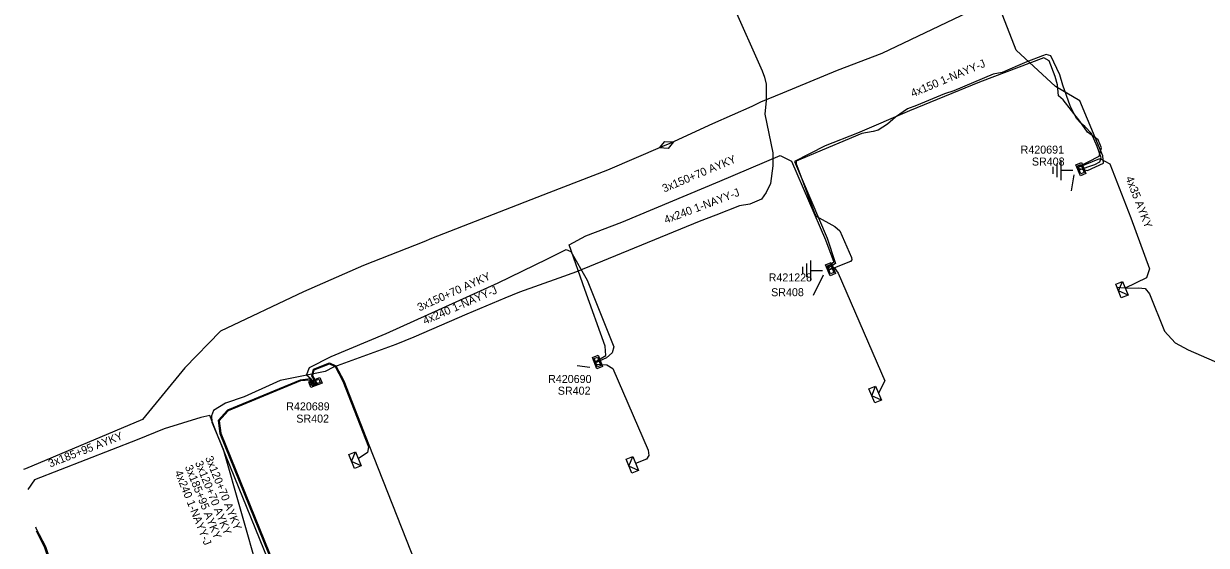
# Model space of a CAD drawing. Extents: x -540028 to -538776, y -1157064 to -1155670.
# Drawn here: x -539966.3 to -539818.5, y -1156244.1 to -1156179 of the extents above; entities that cross this region are included whole.
import ezdxf

# ---------------------------------------------------------------- set-up
doc = ezdxf.new("R2010")
doc.units = 0
for name, color, linetype in [('Vrstva 15', 7, 'Continuous'), ('Vrstva 19', 7, 'Continuous'), ('Vrstva 2', 7, 'Continuous'), ('Vrstva 28', 7, 'Continuous'), ('Vrstva 29', 7, 'Continuous'), ('Vrstva 30', 7, 'Continuous'), ('Vrstva 31', 7, 'Continuous'), ('Vrstva 5', 7, 'Continuous'), ('Vrstva 52', 7, 'Continuous'), ('Vrstva 59', 7, 'Continuous'), ('Vrstva 6', 7, 'Continuous'), ('Vrstva 9', 7, 'Continuous')]:
    doc.layers.add(name, color=color, linetype=linetype)

# ---------------------------------------------------------------- blocks, each defined once
blk = doc.blocks.new('17')
at = {"layer": 'Vrstva 2'}
blk.add_lwpolyline([(-1.875, 0), (0, 0.9375), (1.875, 0), (0, -0.9375)], close=True, dxfattribs=at)
blk = doc.blocks.new('132')
at = {"layer": 'Vrstva 2'}
for points in [[(-1.5, 1.5), (1.5, 1.5), (1.5, 0), (-1.5, 0)], [(-1.1, 1.2), (1.1, 1.2), (1.1, 0.3), (-1.1, 0.3)]]:
    blk.add_lwpolyline(points, close=True, dxfattribs=at)
blk = doc.blocks.new('23')
at = {"layer": 'Vrstva 2'}
blk.add_lwpolyline([(1.875, -1.8), (-1.875, -1.8), (-1.875, 0), (1.875, 0)], close=True, dxfattribs=at)
blk.add_lwpolyline([(1.875, 0), (0, -1.8), (-1.875, 0)], dxfattribs=at)
blk = doc.blocks.new('11')
at = {"layer": 'Vrstva 2'}
for p, q in [((0, -4.3), (0, -1.3)), ((-2.5, -4.3), (2.5, -4.3)), ((-1.7, -5.3), (1.7, -5.3)), ((-0.9, -6.3), (0.9, -6.3))]:
    blk.add_line(p, q, dxfattribs=at)

msp = doc.modelspace()

# ---------------------------------------------------------------- linework, layer by layer
at = {"layer": 'Vrstva 5'}
for points in [[(-539834.5, -1156197.03), (-539833.31, -1156197.31), (-539831.32, -1156196.41), (-539831.41, -1156195.48), (-539834.3, -1156188.62), (-539837.34, -1156186.81), (-539842.25, -1156182.27), (-539845.64, -1156173.48), (-539848.98, -1156165.28), (-539851.72, -1156160.92)], [(-539877.72, -1156176.54), (-539873.98, -1156184.89), (-539873.7, -1156185.67), (-539873.48, -1156186.52), (-539873.48, -1156187.09), (-539873.5, -1156188.58), (-539873.64, -1156190.3), (-539872.66, -1156195.09), (-539872.65, -1156196.75), (-539872.93, -1156198.93), (-539873.5, -1156200.06), (-539874.08, -1156200.88), (-539875.55, -1156201.51), (-539876.81, -1156201.72), (-539879.78, -1156202.89), (-539881.88, -1156203.69), (-539897.18, -1156209.96), (-539899.42, -1156210.75), (-539904.32, -1156212.53), (-539905.25, -1156212.89), (-539906.15, -1156213.25), (-539910.9, -1156215.24), (-539917.52, -1156218.12), (-539919.76, -1156219.06), (-539927.59, -1156221.86), (-539928.62, -1156222.41), (-539934.23, -1156223.55), (-539935.17, -1156223.94), (-539938.74, -1156225.58), (-539941.06, -1156226.39), (-539942.55, -1156227.29), (-539942.82, -1156227.94), (-539942.76, -1156228.74), (-539941.38, -1156232.1), (-539936.93, -1156247.59)], [(-539848.27, -1156177.59), (-539859.05, -1156182.72), (-539864.62, -1156184.81), (-539871.44, -1156187.67), (-539874.19, -1156188.77), (-539874.37, -1156188.87), (-539875.3, -1156189.31), (-539880.22, -1156191.49), (-539885.53, -1156193.93), (-539886.44, -1156194.34), (-539893.34, -1156197.26), (-539900.64, -1156200.09), (-539915.32, -1156205.82), (-539916.28, -1156206.22), (-539923.81, -1156209.19), (-539931.32, -1156212.47), (-539941.68, -1156217.37), (-539946.15, -1156221.96), (-539951.45, -1156228.42), (-539966.08, -1156234.56), (-539966.3, -1156234.65)], [(-539834.5, -1156197.29), (-539832.42, -1156196.58), (-539831.8, -1156196.23), (-539831.63, -1156195.74), (-539832.12, -1156194.3), (-539832.81, -1156192.68), (-539833.67, -1156191.83), (-539834.12, -1156191.45), (-539834.69, -1156190.83), (-539835.5, -1156189.25), (-539836.4, -1156186.67), (-539836.8, -1156185.39), (-539837.92, -1156182.99), (-539838.51, -1156182.83), (-539838.95, -1156182.98), (-539840.92, -1156183.74), (-539842.09, -1156184.24), (-539844, -1156185.06), (-539845.12, -1156185.3), (-539850.04, -1156187.37), (-539851.2, -1156187.74), (-539854.7, -1156189.2), (-539855.83, -1156189.6), (-539857.32, -1156190.65), (-539858.34, -1156191.52), (-539859.48, -1156192.27), (-539860.11, -1156192.45), (-539861.55, -1156192.68), (-539868.08, -1156195.44), (-539869.76, -1156196.16), (-539869.73, -1156196.5), (-539869.14, -1156198.02), (-539868.69, -1156199.27), (-539867.46, -1156202.64), (-539867.23, -1156203), (-539864.93, -1156204.3), (-539864.3, -1156204.86), (-539862.83, -1156208.17), (-539862.79, -1156208.46), (-539862.97, -1156208.7), (-539865.79, -1156209.79)], [(-539894.95, -1156221.24), (-539893.55, -1156220.43), (-539893.6, -1156219.25), (-539896.15, -1156212.19), (-539898.12, -1156206.58), (-539896.04, -1156205.47), (-539891.52, -1156203.78), (-539879.3, -1156198.64), (-539871.73, -1156195.45), (-539870.34, -1156196.15), (-539866.07, -1156205.96), (-539865.05, -1156208.78), (-539865.88, -1156209.4)], [(-539834.53, -1156196.96), (-539831.77, -1156195.81), (-539830.55, -1156196.49), (-539827.93, -1156203.22), (-539825.58, -1156209.6), (-539825.94, -1156210.72), (-539828.61, -1156212.03)], [(-539929.75, -1156224.13), (-539930.35, -1156223.39), (-539930.96, -1156222.89), (-539930.58, -1156221.91), (-539927.85, -1156220.55), (-539921, -1156217.68), (-539907.01, -1156211.35), (-539900.91, -1156208.39), (-539898.49, -1156207.2), (-539897.9, -1156207.44), (-539895.86, -1156211.03), (-539892.52, -1156219.35), (-539892.74, -1156220.09), (-539893.43, -1156220.72), (-539894.9, -1156221.36)], [(-539929.85, -1156224.17), (-539930.45, -1156223.35), (-539931.74, -1156223.48), (-539940.8, -1156227.24), (-539942, -1156228.53), (-539941.76, -1156230.14), (-539929.6, -1156260.15), (-539927.94, -1156263.7), (-539922.13, -1156271.08), (-539920.05, -1156273.79), (-539918.56, -1156277.25), (-539918.64, -1156280.6), (-539919.35, -1156284.8), (-539918.71, -1156288.03), (-539918.53, -1156290.1), (-539919.21, -1156291.58), (-539920.51, -1156292.49), (-539932.04, -1156296.91), (-539942.01, -1156300.99)], [(-539929.97, -1156224.22), (-539930.51, -1156223.48), (-539931.71, -1156223.6), (-539940.73, -1156227.34), (-539941.88, -1156228.57), (-539941.64, -1156230.11), (-539929.49, -1156260.1), (-539927.84, -1156263.64), (-539922.03, -1156271.01), (-539919.95, -1156273.72), (-539918.44, -1156277.16), (-539918.51, -1156280.66), (-539919.17, -1156284.83), (-539918.59, -1156287.98), (-539918.37, -1156290.17), (-539919.25, -1156291.69), (-539920.45, -1156292.57), (-539931.99, -1156297.03), (-539941.96, -1156301.1)], [(-539942.1, -1156300.77), (-539932.23, -1156296.44), (-539925.21, -1156293.77), (-539920.73, -1156292.42), (-539919.27, -1156291.43), (-539918.72, -1156290.03), (-539919.04, -1156287.79), (-539919.52, -1156284.66), (-539919.01, -1156280.21), (-539919.12, -1156277.49), (-539920.89, -1156274.11), (-539922.63, -1156271.3), (-539928.45, -1156263.92), (-539929.95, -1156260.19), (-539942.08, -1156230.36), (-539943.02, -1156227.9), (-539944.17, -1156228.16), (-539948.74, -1156229.59), (-539952.12, -1156230.94), (-539964.96, -1156235.96), (-539965.78, -1156237.17)], [(-539964.81, -1156241.81), (-539964.72, -1156242.06), (-539963.57, -1156244.25), (-539961.69, -1156249.79), (-539961.38, -1156250.13), (-539961.04, -1156250.23), (-539959.94, -1156250.32), (-539959.56, -1156250.72), (-539959.07, -1156251.81)], [(-539959.37, -1156251.58), (-539959.72, -1156250.84), (-539960.04, -1156250.52), (-539961.08, -1156250.43), (-539961.48, -1156250.31), (-539961.83, -1156249.93), (-539963.68, -1156244.3), (-539964.69, -1156242.37)]]:
    msp.add_lwpolyline(points, dxfattribs=at)
at = {"layer": 'Vrstva 52'}
for points in [[(-539865.77, -1156209.68), (-539864.99, -1156209.45), (-539864.49, -1156210.14), (-539858.67, -1156223.58), (-539859.45, -1156225.11)], [(-539828.61, -1156212.03), (-539826.96, -1156211.96), (-539826.13, -1156212.07), (-539825.59, -1156212.71), (-539823.69, -1156217.36), (-539822.37, -1156218.83), (-539820.76, -1156219.73), (-539815.89, -1156221.84), (-539810.28, -1156224.66), (-539808.21, -1156225.38), (-539806.21, -1156224.36), (-539801.84, -1156222.64), (-539801.29, -1156221.99)], [(-539929.63, -1156224.08), (-539930.26, -1156222.95), (-539930.08, -1156222.12), (-539928.08, -1156221.32), (-539927.28, -1156221.72), (-539926.29, -1156223.58), (-539923.17, -1156231.59), (-539917.33, -1156246.36), (-539917.23, -1156247.61), (-539918.46, -1156248.28)], [(-539929.51, -1156224.04), (-539930.14, -1156222.94), (-539929.98, -1156222.21), (-539928.09, -1156221.46), (-539927.37, -1156221.81), (-539926.4, -1156223.63), (-539923.2, -1156231.84), (-539923.34, -1156232.53), (-539924.48, -1156233.32)], [(-539894.85, -1156221.49), (-539893.41, -1156221.6), (-539892.66, -1156222.05), (-539888.26, -1156232.26), (-539888.15, -1156232.92), (-539888.44, -1156233.35), (-539889.82, -1156233.91)]]:
    msp.add_lwpolyline(points, dxfattribs=at)
at = {"layer": 'Vrstva 59'}
for points in [[(-539835.04, -1156197.85), (-539835.38, -1156199.87)], [(-539866.38, -1156210.37), (-539867.61, -1156212.94)], [(-539828.61, -1156212.03), (-539829.72, -1156211.94)], [(-539895.55, -1156221.9), (-539897.12, -1156221.69)]]:
    msp.add_lwpolyline(points, dxfattribs=at)
at = {"layer": 'Vrstva 9'}
msp.add_lwpolyline([(-539834.55, -1156196.91), (-539831.86, -1156195.54), (-539831.59, -1156194.47), (-539831.98, -1156193.49), (-539833.33, -1156192.52), (-539834.27, -1156191.15), (-539836.37, -1156188.5), (-539836.95, -1156187.98), (-539837.08, -1156186.61), (-539837.35, -1156185.57), (-539838.12, -1156183.63), (-539838.78, -1156183.23), (-539846.83, -1156186.29), (-539855.59, -1156189.86), (-539862.07, -1156192.64), (-539866.12, -1156194.24), (-539869.95, -1156196.18), (-539865.87, -1156205.78), (-539864.83, -1156208.92), (-539865.82, -1156209.56)], dxfattribs=at)

# ---------------------------------------------------------------- block references
at = {"layer": 'Vrstva 15', "xscale": 0.5, "yscale": 0.5, "rotation": -90}
for p in [(-539834.5, -1156197.29), (-539865.79, -1156209.79)]:
    msp.add_blockref('11', p, dxfattribs=at)
at = {"layer": 'Vrstva 19', "xscale": 0.5000000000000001, "yscale": 0.5, "rotation": -156.2819888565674}
msp.add_blockref('17', (-539885.95, -1156194.12), dxfattribs=at)
at = {"layer": 'Vrstva 28'}
for p, xscale, yscale, rotation in [((-539834.5, -1156197.29), 0.5000000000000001, 0.4999999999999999, -68.29706668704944), ((-539865.79, -1156209.79), 0.49999999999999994, 0.5, -67.54358337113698), ((-539894.92, -1156221.37), 0.5, 0.49999999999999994, -67.97787773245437), ((-539929.7, -1156224.14), 0.5, 0.5000000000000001, 21.57058330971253)]:
    msp.add_blockref('132', p, dxfattribs=dict(at, xscale=xscale, yscale=yscale, rotation=rotation))
at = {"layer": 'Vrstva 31'}
for p, xscale, yscale, rotation in [((-539828.61, -1156212.03), 0.5000000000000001, 0.4999999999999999, -68.29706668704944), ((-539859.45, -1156225.12), 0.49999999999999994, 0.5000000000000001, -67.542058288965), ((-539924.48, -1156233.32), 0.5, 0.5, -67.93216398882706), ((-539889.82, -1156233.91), 0.5, 0.49999999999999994, -67.97787773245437)]:
    msp.add_blockref('23', p, dxfattribs=dict(at, xscale=xscale, yscale=yscale, rotation=rotation))

# ---------------------------------------------------------------- texts
at = {"layer": 'Vrstva 29'}
for s, p in [('R420691', (-539841.69, -1156195.21)), ('R421228', (-539873.18, -1156211.17)), ('R420690', (-539900.75, -1156223.85)), ('R420689', (-539933.48, -1156227.27))]:
    msp.add_text(s, height=1, dxfattribs=at).set_placement(p)
at = {"layer": 'Vrstva 30'}
for s, rotation, p in [('SR408', 0.063, (-539840.28, -1156196.7)), ('SR408', 0.168, (-539872.87, -1156213.02)), ('SR402', 0.183, (-539899.53, -1156225.32)), ('SR402', 0.086, (-539932.22, -1156228.8))]:
    msp.add_text(s, height=1, rotation=rotation, dxfattribs=at).set_placement(p)
at = {"layer": 'Vrstva 6'}
for s, rotation, p in [('4x150 1-NAYY-J', 22.818, (-539855.17, -1156188.18)), ('3x150+70 AYKY', 22.829, (-539886.24, -1156200.08)), ('4x240 1-NAYY-J', 20.854, (-539886.03, -1156203.98)), ('4x35 AYKY', 291.23, (-539828.59, -1156198.25)), ('3x150+70 AYKY', 24.328, (-539916.82, -1156214.92)), ('4x240 1-NAYY-J', 23.511, (-539916.14, -1156216.58)), ('3x185+95 AYKY', 21.353, (-539962.99, -1156234.42)), ('3x120+70 AYKY', 292.049, (-539944.9, -1156233.8)), ('3x120+70 AYKY', 292.05, (-539943.63, -1156233.2)), ('4x240 1-NAYY-J', 292.145, (-539947.45, -1156234.99)), ('3x185+95 AYKY', 292.145, (-539946.17, -1156234.32))]:
    msp.add_text(s, height=1, rotation=rotation, dxfattribs=at).set_placement(p)

doc.saveas('drawing.dxf')
